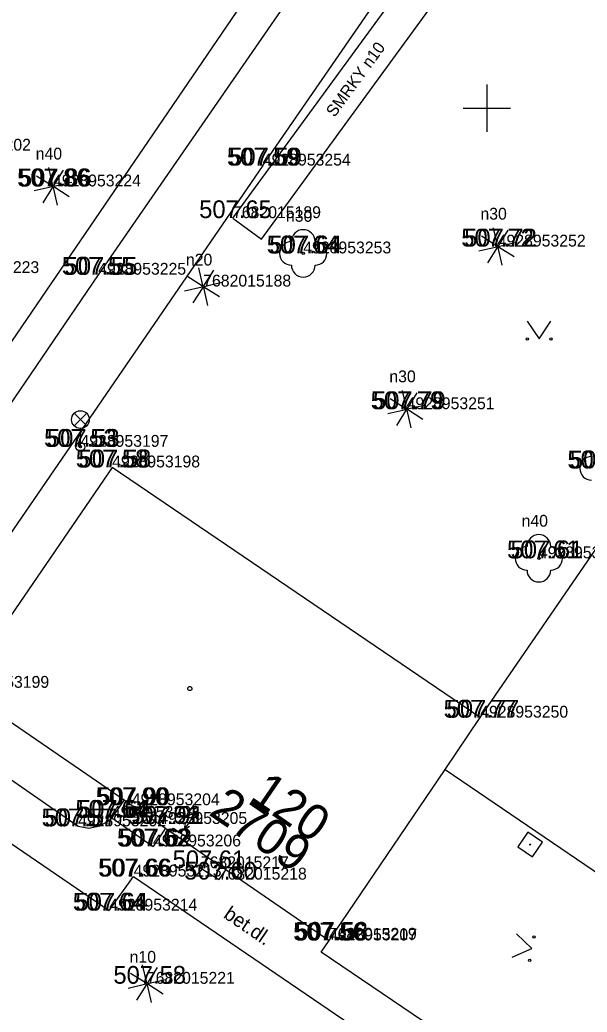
# Model space of a CAD drawing. Extents: x -669251 to -668549, y -1128351 to -1127698.
# Drawn here: x -668719.74 to -668695.76, y -1128038.19 to -1127996.27 of the extents above; entities that cross this region are included whole.
import ezdxf

# ---------------------------------------------------------------- set-up
doc = ezdxf.new("R2010")
doc.units = 0
for name, color, linetype in [('Vrstva 1', 7, 'Continuous'), ('Vrstva 10', 7, 'Continuous'), ('Vrstva 11', 7, 'Continuous'), ('Vrstva 14', 7, 'Continuous'), ('Vrstva 2', 7, 'Continuous'), ('Vrstva 21', 7, 'Continuous'), ('Vrstva 22', 7, 'Continuous'), ('Vrstva 24', 7, 'Continuous'), ('Vrstva 26', 7, 'Continuous'), ('Vrstva 3', 7, 'Continuous'), ('Vrstva 33', 7, 'Continuous'), ('Vrstva 36', 7, 'Continuous'), ('Vrstva 40', 7, 'Continuous'), ('Vrstva 43', 7, 'Continuous'), ('Vrstva 44', 7, 'Continuous'), ('Vrstva 47', 7, 'Continuous'), ('Vrstva 5', 7, 'Continuous'), ('Vrstva 58', 7, 'Continuous'), ('Vrstva 6', 7, 'Continuous'), ('Vrstva 61', 7, 'Continuous')]:
    doc.layers.add(name, color=color, linetype=linetype)

msp = doc.modelspace()

# ---------------------------------------------------------------- linework, layer by layer
at = {"layer": 'Vrstva 1'}
for p, q in [((-668709.47, -1128002.43), (-668709.47, -1128002.43)), ((-668718.34, -1128003.31), (-668718.34, -1128003.31)), ((-668710.73, -1128004.65), (-668710.73, -1128004.65)), ((-668699.54, -1128005.85), (-668699.54, -1128005.85)), ((-668707.76, -1128006.14), (-668707.76, -1128006.14)), ((-668716.43, -1128007.04), (-668716.43, -1128007.04)), ((-668711.99, -1128007.54), (-668711.99, -1128007.54)), ((-668703.39, -1128012.72), (-668703.39, -1128012.72)), ((-668717.18, -1128014.31), (-668717.18, -1128014.31)), ((-668715.84, -1128015.18), (-668715.84, -1128015.18)), ((-668697.8, -1128019.02), (-668697.8, -1128019.02)), ((-668700.28, -1128025.75), (-668700.28, -1128025.75)), ((-668715.01, -1128029.45), (-668715.01, -1128029.45)), ((-668715.85, -1128029.98), (-668715.85, -1128029.98)), ((-668713.85, -1128030.24), (-668713.85, -1128030.24)), ((-668717.28, -1128030.34), (-668717.28, -1128030.34)), ((-668714.11, -1128031.19), (-668714.11, -1128031.19)), ((-668712.09, -1128032.11), (-668712.09, -1128032.11)), ((-668714.93, -1128032.46), (-668714.93, -1128032.46)), ((-668711.33, -1128032.59), (-668711.33, -1128032.59)), ((-668715.96, -1128033.9), (-668715.96, -1128033.9)), ((-668706.68, -1128035.13), (-668706.68, -1128035.13)), ((-668706.67, -1128035.16), (-668706.67, -1128035.16)), ((-668714.37, -1128036.99), (-668714.37, -1128036.99))]:
    msp.add_line(p, q, dxfattribs=at)
at = {"layer": 'Vrstva 10'}
for p, q in [((-668701.78, -1127985.84), (-668716.43, -1128007.04)), ((-668709.47, -1128002.43), (-668700.65, -1127989.62)), ((-668709.47, -1128002.43), (-668724.44, -1128024.23)), ((-668716.43, -1128007.04), (-668727.855, -1128023.819)), ((-668724.12, -1128025.6), (-668717.28, -1128030.34)), ((-668725.43, -1128027.43), (-668715.96, -1128033.9)), ((-668715.96, -1128033.9), (-668714.93, -1128032.46)), ((-668714.93, -1128032.46), (-668695.76, -1128045.51)), ((-668707.009, -1128035.655), (-668706.67, -1128035.16)), ((-668694.69, -1128043.96), (-668707.009, -1128035.655))]:
    msp.add_line(p, q, dxfattribs=at)
msp.add_lwpolyline([(-668717.28, -1128030.34), (-668716.821, -1128030.412), (-668716.365, -1128030.325), (-668715.965, -1128030.089), (-668715.85, -1128029.98)], dxfattribs=at)
at = {"layer": 'Vrstva 11'}
for p, q in [((-668715.333, -1128029.228), (-668715.85, -1128029.98)), ((-668715.85, -1128029.98), (-668714.11, -1128031.19)), ((-668713.583, -1128030.423), (-668714.11, -1128031.19)), ((-668711.78, -1128031.658), (-668712.09, -1128032.11)), ((-668712.09, -1128032.11), (-668711.33, -1128032.59)), ((-668711.039, -1128032.166), (-668711.33, -1128032.59))]:
    msp.add_line(p, q, dxfattribs=at)
at = {"layer": 'Vrstva 14'}
msp.add_line((-668728.76, -1128022.56), (-668704.23, -1127986.63), dxfattribs=at)
at = {"layer": 'Vrstva 21'}
for p, q in [((-668710.73, -1128004.65), (-668699.45, -1127989.2)), ((-668709.519, -1128005.534), (-668699.087, -1127991.247)), ((-668710.73, -1128004.65), (-668709.519, -1128005.534))]:
    msp.add_line(p, q, dxfattribs=at)
at = {"layer": 'Vrstva 22'}
for p, q in [((-668718.348, -1128003.27), (-668718.52, -1128002.516)), ((-668718.374, -1128003.29), (-668719.03, -1128002.876)), ((-668717.906, -1128002.62), (-668718.32, -1128003.276)), ((-668719.134, -1128003.49), (-668718.38, -1128003.318)), ((-668718.36, -1128003.344), (-668718.774, -1128004)), ((-668718.332, -1128003.35), (-668718.16, -1128004.104)), ((-668717.65, -1128003.744), (-668718.306, -1128003.33)), ((-668718.3, -1128003.302), (-668717.546, -1128003.13)), ((-668699.548, -1128005.81), (-668699.72, -1128005.056)), ((-668699.574, -1128005.83), (-668700.23, -1128005.416)), ((-668699.106, -1128005.16), (-668699.52, -1128005.816)), ((-668700.334, -1128006.03), (-668699.58, -1128005.858)), ((-668699.56, -1128005.884), (-668699.974, -1128006.54)), ((-668699.532, -1128005.89), (-668699.36, -1128006.644)), ((-668698.85, -1128006.284), (-668699.506, -1128005.87)), ((-668699.5, -1128005.842), (-668698.746, -1128005.67)), ((-668711.998, -1128007.5), (-668712.17, -1128006.746)), ((-668712.024, -1128007.52), (-668712.68, -1128007.106)), ((-668711.556, -1128006.85), (-668711.97, -1128007.506)), ((-668712.784, -1128007.72), (-668712.03, -1128007.548)), ((-668712.01, -1128007.574), (-668712.424, -1128008.23)), ((-668711.982, -1128007.58), (-668711.81, -1128008.334)), ((-668711.3, -1128007.974), (-668711.956, -1128007.56)), ((-668711.95, -1128007.532), (-668711.196, -1128007.36)), ((-668703.398, -1128012.68), (-668703.57, -1128011.926)), ((-668702.956, -1128012.03), (-668703.37, -1128012.686)), ((-668703.424, -1128012.7), (-668704.08, -1128012.286)), ((-668703.35, -1128012.712), (-668702.596, -1128012.54)), ((-668704.184, -1128012.9), (-668703.43, -1128012.728)), ((-668703.41, -1128012.754), (-668703.824, -1128013.41)), ((-668703.382, -1128012.76), (-668703.21, -1128013.514)), ((-668702.7, -1128013.154), (-668703.356, -1128012.74)), ((-668714.378, -1128036.95), (-668714.55, -1128036.196)), ((-668713.936, -1128036.3), (-668714.35, -1128036.956)), ((-668714.404, -1128036.97), (-668715.06, -1128036.556)), ((-668714.33, -1128036.982), (-668713.576, -1128036.81)), ((-668715.164, -1128037.17), (-668714.41, -1128036.998)), ((-668714.39, -1128037.024), (-668714.804, -1128037.68)), ((-668714.362, -1128037.03), (-668714.19, -1128037.784)), ((-668713.68, -1128037.424), (-668714.336, -1128037.01))]:
    msp.add_line(p, q, dxfattribs=at)
for centre, radius in [((-668718.34, -1128003.31), 0.04), ((-668699.54, -1128005.85), 0.04), ((-668707.76, -1128006.14), 0.05), ((-668711.99, -1128007.54), 0.04), ((-668703.39, -1128012.72), 0.04), ((-668697.8, -1128019.02), 0.05), ((-668714.37, -1128036.99), 0.04)]:
    msp.add_circle(centre, radius, dxfattribs=at)
for centre, start, end in [((-668707.76, -1128005.64), 0, 180), ((-668708.26, -1128006.14), 90, 270), ((-668707.26, -1128006.14), 270, 90), ((-668707.76, -1128006.64), 180, 0), ((-668695.57, -1128015.22), 90, 270), ((-668697.8, -1128018.52), 0, 180), ((-668698.3, -1128019.02), 90, 270), ((-668697.3, -1128019.02), 270, 90), ((-668697.8, -1128019.52), 180, 0)]:
    msp.add_arc(centre, 0.5, start, end, dxfattribs=at)
at = {"layer": 'Vrstva 24'}
for p, q in [((-668712.369, -1128029.405), (-668712.723, -1128029.922)), ((-668712.304, -1128029.754), (-668712.799, -1128030.475)), ((-668712.723, -1128029.922), (-668712.304, -1128029.754)), ((-668712.751, -1128030.211), (-668712.799, -1128030.475)), ((-668713.355, -1128030.579), (-668713.242, -1128030.414)), ((-668713.242, -1128030.414), (-668712.582, -1128030.867)), ((-668712.799, -1128030.475), (-668712.57, -1128030.336)), ((-668712.582, -1128030.867), (-668712.695, -1128031.031))]:
    msp.add_line(p, q, dxfattribs=at)
at = {"layer": 'Vrstva 26'}
msp.add_lwpolyline([(-668698.684, -1128031.21), (-668698.063, -1128031.631), (-668697.642, -1128031.01), (-668698.263, -1128030.589)], close=True, dxfattribs=at)
msp.add_circle((-668698.163, -1128031.11), 0.02, dxfattribs=at)
at = {"layer": 'Vrstva 33'}
for p, q in [((-668717.445, -1128012.895), (-668716.915, -1128013.425)), ((-668717.445, -1128013.425), (-668716.915, -1128012.895)), ((-668717.18, -1128014.31), (-668717.18, -1128013.535))]:
    msp.add_line(p, q, dxfattribs=at)
for centre, radius in [((-668717.18, -1128013.16), 0.375), ((-668717.18, -1128014.31), 0.19), ((-668717.18, -1128014.31), 0.05)]:
    msp.add_circle(centre, radius, dxfattribs=at)
at = {"layer": 'Vrstva 36'}
for p, q in [((-668698.29, -1128009.005), (-668697.79, -1128009.755)), ((-668697.79, -1128009.755), (-668697.29, -1128009.005)), ((-668698.096, -1128035.506), (-668698.742, -1128034.878)), ((-668698.925, -1128035.861), (-668698.096, -1128035.506))]:
    msp.add_line(p, q, dxfattribs=at)
for centre in [(-668698.291, -1128009.755), (-668697.291, -1128009.755), (-668698.005, -1128035.014), (-668698.187, -1128035.998)]:
    msp.add_circle(centre, 0.05, dxfattribs=at)
at = {"layer": 'Vrstva 5'}
for p, q in [((-668700.28, -1128025.75), (-668688.674, -1128008.827)), ((-668715.84, -1128015.18), (-668722.22, -1128024.49)), ((-668700.28, -1128025.75), (-668715.84, -1128015.18)), ((-668722.22, -1128024.49), (-668715.333, -1128029.228)), ((-668701.766, -1128027.939), (-668700.28, -1128025.75)), ((-668706.67, -1128035.16), (-668701.766, -1128027.939)), ((-668701.766, -1128027.939), (-668693.93, -1128033.26)), ((-668715.333, -1128029.228), (-668715.01, -1128029.45)), ((-668713.85, -1128030.24), (-668713.583, -1128030.423)), ((-668713.583, -1128030.423), (-668711.78, -1128031.658)), ((-668711.78, -1128031.658), (-668711.039, -1128032.166)), ((-668711.039, -1128032.166), (-668706.67, -1128035.16))]:
    msp.add_line(p, q, dxfattribs=at)
at = {"layer": 'Vrstva 58'}
msp.add_circle((-668712.554, -1128024.521), 0.0875, dxfattribs=at)
at = {"layer": 'Vrstva 6'}
msp.add_line((-668715.01, -1128029.45), (-668713.85, -1128030.24), dxfattribs=at)
at = {"layer": 'Vrstva 61'}
for p, q in [((-668700, -1127999), (-668700, -1128001)), ((-668701, -1128000), (-668699, -1128000))]:
    msp.add_line(p, q, dxfattribs=at)

# ---------------------------------------------------------------- texts
at = {"layer": 'Vrstva 2'}
for s, p in [('7682015202', (-668722.99, -1128001.8)), ('4928953254', (-668709.47, -1128002.43)), ('4928953224', (-668718.34, -1128003.31)), ('7682015189', (-668710.73, -1128004.65)), ('4928953252', (-668699.54, -1128005.85)), ('4928953253', (-668707.76, -1128006.14)), ('4928953223', (-668722.64, -1128006.97)), ('4928953225', (-668716.43, -1128007.04)), ('7682015188', (-668711.99, -1128007.54)), ('4928953251', (-668703.39, -1128012.72)), ('4928953197', (-668717.18, -1128014.31)), ('4928953198', (-668715.84, -1128015.18)), ('4928953249', (-668697.8, -1128019.02)), ('4928953199', (-668722.22, -1128024.49)), ('4928953250', (-668700.28, -1128025.75)), ('4928953204', (-668715.01, -1128029.45)), ('4928953202', (-668717.28, -1128030.34)), ('4928953203', (-668715.85, -1128029.98)), ('4928953205', (-668713.85, -1128030.24)), ('4928953206', (-668714.11, -1128031.19)), ('7682015217', (-668712.09, -1128032.11)), ('4928953213', (-668714.93, -1128032.46)), ('7682015218', (-668711.33, -1128032.59)), ('4928953214', (-668715.96, -1128033.9)), ('4928953207', (-668706.67, -1128035.16)), ('7682015219', (-668706.68, -1128035.13)), ('7682015221', (-668714.37, -1128036.99))]:
    msp.add_text(s, height=0.5, dxfattribs=at).set_placement(p)
at = {"layer": 'Vrstva 3'}
for s, p in [('507.59 ', (-668710.986, -1128002.43)), ('507.59 ', (-668710.888, -1128002.43)), ('507.86 ', (-668719.856, -1128003.31)), ('507.86 ', (-668719.778, -1128003.31)), ('507.65 ', (-668712.159, -1128004.65)), ('507.72 ', (-668701.079, -1128005.85)), ('507.72 ', (-668700.955, -1128005.85)), ('507.64 ', (-668709.303, -1128006.14)), ('507.64 ', (-668709.189, -1128006.14)), ('507.55 ', (-668717.965, -1128007.04)), ('507.55 ', (-668717.845, -1128007.04)), ('507.79 ', (-668704.91, -1128012.72)), ('507.79 ', (-668704.808, -1128012.72)), ('507.53 ', (-668718.715, -1128014.31)), ('507.53 ', (-668718.595, -1128014.31)), ('507.58 ', (-668717.375, -1128015.18)), ('507.58 ', (-668717.255, -1128015.18)), ('507.92 ', (-668696.594, -1128015.22)), ('507.92 ', (-668696.487, -1128015.22)), ('507.61 ', (-668699.146, -1128019.02)), ('507.61 ', (-668698.992, -1128019.02)), ('507.77 ', (-668701.827, -1128025.75)), ('507.77 ', (-668701.695, -1128025.75)), ('507.90 ', (-668716.534, -1128029.45)), ('507.90 ', (-668716.463, -1128029.45)), ('507.64 ', (-668717.393, -1128029.98)), ('507.64 ', (-668717.279, -1128029.98)), ('507.57 ', (-668718.823, -1128030.34)), ('507.57 ', (-668718.695, -1128030.34)), ('507.91 ', (-668715.196, -1128030.24)), ('507.91 ', (-668715.03, -1128030.24)), ('507.62 ', (-668715.634, -1128031.19)), ('507.62 ', (-668715.539, -1128031.19)), ('507.61 ', (-668713.282, -1128032.11)), ('507.66 ', (-668716.434, -1128032.46)), ('507.66 ', (-668716.382, -1128032.46)), ('507.60 ', (-668712.794, -1128032.59)), ('507.64 ', (-668717.503, -1128033.9)), ('507.64 ', (-668717.389, -1128033.9)), ('507.56 ', (-668708.186, -1128035.16)), ('507.56 ', (-668708.108, -1128035.16)), ('507.58 ', (-668708.095, -1128035.13)), ('507.58 ', (-668715.785, -1128036.99))]:
    msp.add_text(s, height=0.75, dxfattribs=at).set_placement(p)
at = {"layer": 'Vrstva 40'}
msp.add_text('bet.dl.', height=0.6, rotation=325.7549, dxfattribs=at).set_placement((-668711.171, -1128034.172))
at = {"layer": 'Vrstva 43'}
msp.add_text('2709', height=1.5, rotation=325.5796, dxfattribs=at).set_placement((-668711.803, -1128029.824))
at = {"layer": 'Vrstva 44'}
msp.add_text('120', height=1.5, rotation=325.5796, dxfattribs=at).set_placement((-668710.081, -1128029.186))
at = {"layer": 'Vrstva 47'}
msp.add_text('SMRKY n10', height=0.5, rotation=53.8669, dxfattribs=at).set_placement((-668706.436, -1128000.418))
for s, height, p in [('n40', 0.5, (-668719.07, -1128002.174)), ('n30', 0.5, (-668700.27, -1128004.714)), ('n30', 0.499, (-668708.489, -1128004.804)), ('n20', 0.5, (-668712.72, -1128006.654)), ('n30', 0.5, (-668704.12, -1128011.584)), ('n40', 0.499, (-668698.529, -1128017.684)), ('n10', 0.5, (-668715.1, -1128036.104))]:
    msp.add_text(s, height=height, dxfattribs=at).set_placement(p)

doc.saveas('drawing.dxf')
